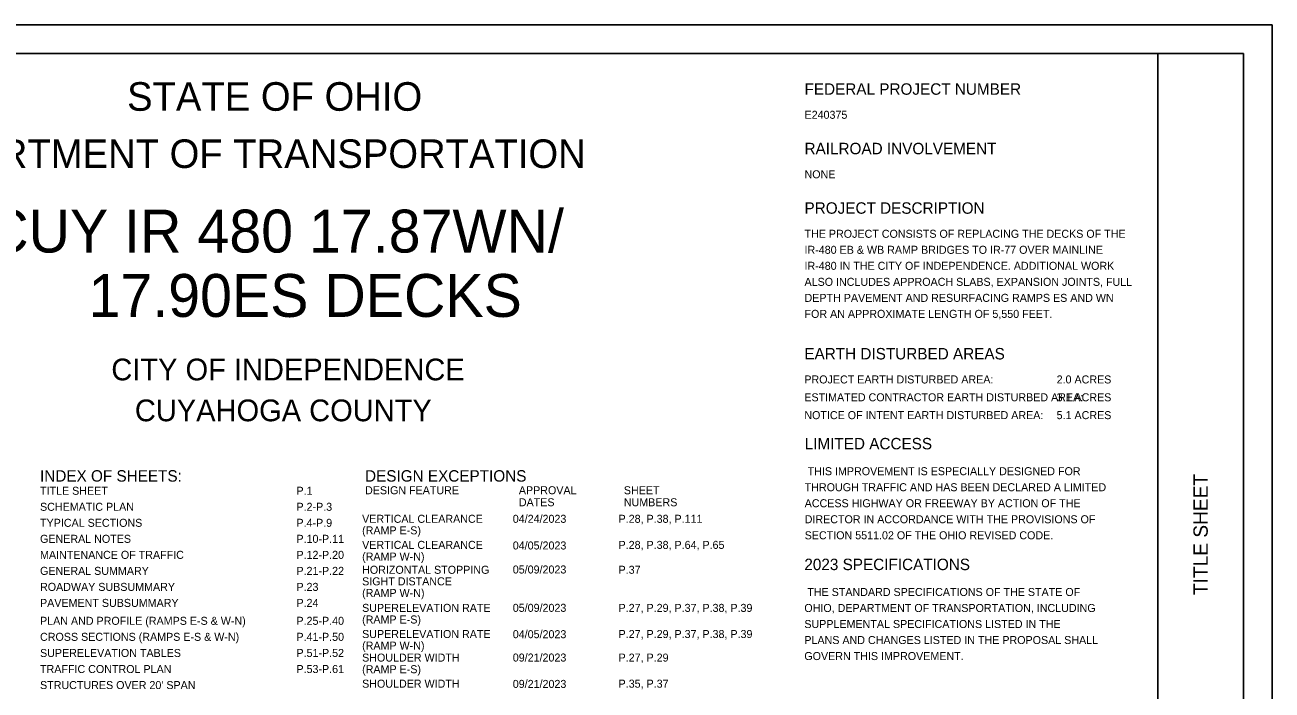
# Model space of a CAD drawing. Extents: x 0 to 34, y -1.2 to 22.
# Drawn here: x 12.18 to 34, y 10.38 to 22 of the extents above; entities that cross this region are included whole.
import ezdxf

# ---------------------------------------------------------------- set-up
doc = ezdxf.new("R2010")
doc.units = 0
for name, color, linetype in [('SH_Border', 7, 'Continuous'), ('SH_Cut_Line', 7, 'Continuous'), ('SH_Data', 7, 'Continuous')]:
    doc.layers.add(name, color=color, linetype=linetype)

msp = doc.modelspace()

# ---------------------------------------------------------------- linework, layer by layer
at = {"layer": 'SH_Border'}
msp.add_line((32, 0.5), (32, 21.5), dxfattribs=at)
msp.add_lwpolyline([(1.5, 21.5), (33.5, 21.5), (33.5, 0.5), (1.5, 0.5)], close=True, dxfattribs=at)
at = {"layer": 'SH_Cut_Line'}
msp.add_lwpolyline([(0, 0), (34, 0), (34, 22), (0, 22)], close=True, dxfattribs=at)

# ---------------------------------------------------------------- texts
for s, height, p in [('STATE OF OHIO', 0.5, (13.968, 20.5)), ('FEDERAL PROJECT NUMBER', 0.2, (25.82, 20.78)), ('E240375', 0.14, (25.82, 20.36)), ('DEPARTMENT OF TRANSPORTATION', 0.5, (9.92, 19.5)), ('RAILROAD INVOLVEMENT', 0.2, (25.82, 19.74)), ('NONE', 0.14, (25.82, 19.32)), ('CUY IR 480 17.87WN/', 0.75, (11.521, 18.022)), ('PROJECT DESCRIPTION', 0.2, (25.82, 18.7)), ('THE PROJECT CONSISTS OF REPLACING THE DECKS OF THE ', 0.14, (25.82, 18.28)), ('IR-480 EB & WB RAMP BRIDGES TO IR-77 OVER MAINLINE ', 0.14, (25.82, 18)), ('IR-480 IN THE CITY OF INDEPENDENCE. ADDITIONAL WORK ', 0.14, (25.82, 17.72)), ('17.90ES DECKS', 0.75, (13.293, 16.897)), ('ALSO INCLUDES APPROACH SLABS, EXPANSION JOINTS, FULL ', 0.14, (25.82, 17.44)), ('DEPTH PAVEMENT AND RESURFACING RAMPS ES AND WN ', 0.14, (25.82, 17.16)), ('FOR AN APPROXIMATE LENGTH OF 5,550 FEET.', 0.14, (25.82, 16.88)), ('CITY OF INDEPENDENCE', 0.38, (13.692, 15.788)), ('EARTH DISTURBED AREAS', 0.2, (25.817, 16.154)), ('PROJECT EARTH DISTURBED AREA:', 0.14, (25.817, 15.734)), ('2.0 ACRES', 0.14, (30.231, 15.734)), ('ESTIMATED CONTRACTOR EARTH DISTURBED AREA:', 0.14, (25.817, 15.422)), ('3.1 ACRES', 0.14, (30.231, 15.422)), ('CUYAHOGA COUNTY', 0.38, (14.104, 15.073)), ('NOTICE OF INTENT EARTH DISTURBED AREA:', 0.14, (25.817, 15.11)), ('5.1 ACRES', 0.14, (30.231, 15.11)), ('LIMITED ACCESS', 0.2, (25.823, 14.582)), ('INDEX OF SHEETS:', 0.2, (12.445, 14.018)), ('DESIGN EXCEPTIONS', 0.2, (18.131, 14.018)), (' THIS IMPROVEMENT IS ESPECIALLY DESIGNED FOR', 0.14, (25.823, 14.13)), ('THROUGH TRAFFIC AND HAS BEEN DECLARED A LIMITED', 0.14, (25.823, 13.85)), ('TITLE SHEET', 0.14, (12.445, 13.788)), ('P.1', 0.14, (16.931, 13.788)), ('DESIGN FEATURE', 0.14, (18.131, 13.797)), ('APPROVAL', 0.14, (20.822, 13.797)), ('SHEET', 0.14, (22.659, 13.797)), ('SCHEMATIC PLAN', 0.14, (12.445, 13.508)), ('P.2-P.3', 0.14, (16.931, 13.508)), ('DATES', 0.14, (20.822, 13.587)), ('NUMBERS', 0.14, (22.659, 13.587)), ('ACCESS HIGHWAY OR FREEWAY BY ACTION OF THE', 0.14, (25.823, 13.57)), ('TYPICAL SECTIONS', 0.14, (12.445, 13.228)), ('P.4-P.9', 0.14, (16.931, 13.228)), ('P.28, P.38, P.111', 0.14, (22.567, 13.298)), ('DIRECTOR IN ACCORDANCE WITH THE PROVISIONS OF', 0.14, (25.823, 13.29)), ('SECTION 5511.02 OF THE OHIO REVISED CODE.', 0.14, (25.823, 13.01)), ('GENERAL NOTES', 0.14, (12.445, 12.948)), ('P.10-P.11', 0.14, (16.931, 12.948)), ('P.28, P.38, P.64, P.65', 0.14, (22.567, 12.842)), ('MAINTENANCE OF TRAFFIC', 0.14, (12.445, 12.668)), ('P.12-P.20', 0.14, (16.931, 12.668)), ('2023 SPECIFICATIONS', 0.2, (25.817, 12.471)), ('GENERAL SUMMARY', 0.14, (12.445, 12.388)), ('P.21-P.22', 0.14, (16.931, 12.388)), ('P.37', 0.14, (22.567, 12.407)), ('ROADWAY SUBSUMMARY', 0.14, (12.445, 12.108)), ('P.23', 0.14, (16.931, 12.108)), (' THE STANDARD SPECIFICATIONS OF THE STATE OF', 0.14, (25.817, 12.019)), ('PAVEMENT SUBSUMMARY', 0.14, (12.445, 11.828)), ('P.24', 0.14, (16.931, 11.828)), ('P.27, P.29, P.37, P.38, P.39', 0.14, (22.567, 11.741)), ('OHIO, DEPARTMENT OF TRANSPORTATION, INCLUDING', 0.14, (25.817, 11.739)), ('PLAN AND PROFILE (RAMPS E-S & W-N)', 0.14, (12.445, 11.515)), ('P.25-P.40', 0.14, (16.931, 11.515)), ('SUPPLEMENTAL SPECIFICATIONS LISTED IN THE', 0.14, (25.817, 11.459)), ('CROSS SECTIONS (RAMPS E-S & W-N)', 0.14, (12.445, 11.235)), ('P.41-P.50', 0.14, (16.931, 11.235)), ('P.27, P.29, P.37, P.38, P.39', 0.14, (22.567, 11.284)), ('PLANS AND CHANGES LISTED IN THE PROPOSAL SHALL', 0.14, (25.817, 11.179)), ('SUPERELEVATION TABLES', 0.14, (12.445, 10.953)), ('P.51-P.52', 0.14, (16.931, 10.953)), ('P.27, P.29', 0.14, (22.567, 10.872)), ('GOVERN THIS IMPROVEMENT.', 0.14, (25.817, 10.899)), ('TRAFFIC CONTROL PLAN', 0.14, (12.445, 10.672)), ('P.53-P.61', 0.14, (16.931, 10.672)), ("STRUCTURES OVER 20' SPAN", 0.14, (12.445, 10.392)), ('P.35, P.37', 0.14, (22.567, 10.416))]:
    msp.add_text(s, height=height, dxfattribs=at).set_placement(p)
at = {"layer": 'SH_Data'}
msp.add_text('TITLE SHEET', height=0.25, rotation=90, dxfattribs=at).set_placement((32.875, 12.035))
for s, p in [('VERTICAL CLEARANCE', (18.08, 13.298)), ('04/24/2023', (20.716, 13.298)), ('(RAMP E-S)', (18.08, 13.096)), ('VERTICAL CLEARANCE', (18.08, 12.842)), ('04/05/2023', (20.716, 12.832)), ('(RAMP W-N)', (18.08, 12.639)), ('HORIZONTAL STOPPING', (18.08, 12.407)), ('05/09/2023', (20.716, 12.412)), ('SIGHT DISTANCE', (18.08, 12.205)), ('(RAMP W-N)', (18.08, 12.002)), ('SUPERELEVATION RATE', (18.08, 11.741)), ('05/09/2023', (20.716, 11.742)), ('(RAMP E-S)', (18.08, 11.538)), ('SUPERELEVATION RATE', (18.08, 11.284)), ('04/05/2023', (20.716, 11.281)), ('(RAMP W-N)', (18.08, 11.082)), ('SHOULDER WIDTH', (18.08, 10.872)), ('09/21/2023', (20.716, 10.873)), ('(RAMP E-S)', (18.08, 10.669)), ('SHOULDER WIDTH', (18.08, 10.416)), ('09/21/2023', (20.716, 10.412))]:
    msp.add_text(s, height=0.14, dxfattribs=at).set_placement(p)

doc.saveas('drawing.dxf')
